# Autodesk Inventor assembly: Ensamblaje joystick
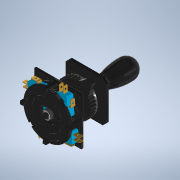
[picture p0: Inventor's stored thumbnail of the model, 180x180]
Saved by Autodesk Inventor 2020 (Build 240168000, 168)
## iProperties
Created: 2022-02
Part Number: Ensamblaje joystick
Document SubType Name: Assembly
Designer: Eresthor
Author: Eresthor
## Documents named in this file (7)
- C:\Users\Eresthor\Documents\Inventor\Pedro\joystick\Ensamblaje joystick.iam
- C:\Users\Eresthor\Documents\Inventor\Pedro\joystick\base palanca 002.ipt
- C:\Users\Eresthor\Documents\Inventor\Pedro\joystick\microinterruptor.ipt
- C:\Users\Eresthor\Documents\Inventor\Pedro\joystick\palanca joystick.iam
- C:\Users\Eresthor\Documents\Inventor\Pedro\joystick\goma joystick.ipt
- C:\Users\Eresthor\Documents\Inventor\Pedro\joystick\rosca palanca.ipt
- C:\Users\Eresthor\Documents\Inventor\Pedro\joystick\base palanca 003.ipt
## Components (9 placed, 6 different names)
1. microinterruptor:1 — Nivelación:3, Nivelación:6, Coincidencia:4, Coincidencia:7
2. microinterruptor:2 — Nivelación:1, Nivelación:4, Nivelación:5, Nivelación:6, Coincidencia:1, Coincidencia:5, Coincidencia:8
3. microinterruptor:3 — Nivelación:1, Nivelación:2, Nivelación:3, Nivelación:4, Coincidencia:2, Coincidencia:3
4. microinterruptor:4 — Nivelación:2, Nivelación:5, Coincidencia:6, Coincidencia:9
5. base palanca 002:1 — Coincidencia:1, Coincidencia:2, Coincidencia:3, Coincidencia:4, Coincidencia:5, Coincidencia:6, Coincidencia:7, Coincidencia:8, Coincidencia:9, Coincidencia:10, Nivelación:7, Coincidencia:11, Coincidencia:16, Coincidencia:17, Coincidencia:18
6. palanca joystick:1 [sub-assembly] — Coincidencia:10, Nivelación:7, Coincidencia:11, Coincidencia:14, Coincidencia:15
7. goma joystick:1 — Coincidencia:12, Coincidencia:13, Coincidencia:14
8. rosca palanca:1 — Coincidencia:12, Coincidencia:13, Coincidencia:15
9. base palanca 003:2 — Coincidencia:16, Coincidencia:17, Coincidencia:18
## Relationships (25: Mate 18, Flush 7)
- Nivelación:1 [Flush]: microinterruptor:2 ↔ microinterruptor:3
- Nivelación:2 [Flush]: microinterruptor:3 ↔ microinterruptor:4
- Nivelación:3 [Flush]: microinterruptor:1 ↔ microinterruptor:3
- Nivelación:4 [Flush]: microinterruptor:2 ↔ microinterruptor:3
- Nivelación:5 [Flush]: microinterruptor:2 ↔ microinterruptor:4
- Nivelación:6 [Flush]: microinterruptor:1 ↔ microinterruptor:2
- Coincidencia:1 [Mate]: microinterruptor:2 ↔ base palanca 002:1
- Coincidencia:2 [Mate]: microinterruptor:3 ↔ base palanca 002:1
- Coincidencia:3 [Mate]: microinterruptor:3 ↔ base palanca 002:1
- Coincidencia:4 [Mate]: microinterruptor:1 ↔ base palanca 002:1
- Coincidencia:5 [Mate]: microinterruptor:2 ↔ base palanca 002:1
- Coincidencia:6 [Mate]: microinterruptor:4 ↔ base palanca 002:1
- Coincidencia:7 [Mate]: microinterruptor:1 ↔ base palanca 002:1
- Coincidencia:8 [Mate]: microinterruptor:2 ↔ base palanca 002:1
- Coincidencia:9 [Mate]: microinterruptor:4 ↔ base palanca 002:1
- Coincidencia:10 [Mate]: base palanca 002:1 ↔ palanca joystick:1
- Nivelación:7 [Flush]: base palanca 002:1 ↔ palanca joystick:1
- Coincidencia:11 [Mate]: base palanca 002:1 ↔ palanca joystick:1
- Coincidencia:12 [Mate]: goma joystick:1 ↔ rosca palanca:1
- Coincidencia:13 [Mate]: goma joystick:1 ↔ rosca palanca:1
- Coincidencia:14 [Mate]: palanca joystick:1 ↔ goma joystick:1
- Coincidencia:15 [Mate]: palanca joystick:1 ↔ rosca palanca:1
- Coincidencia:16 [Mate]: base palanca 002:1 ↔ base palanca 003:2
- Coincidencia:17 [Mate]: base palanca 002:1 ↔ base palanca 003:2
- Coincidencia:18 [Mate]: base palanca 002:1 ↔ base palanca 003:2
